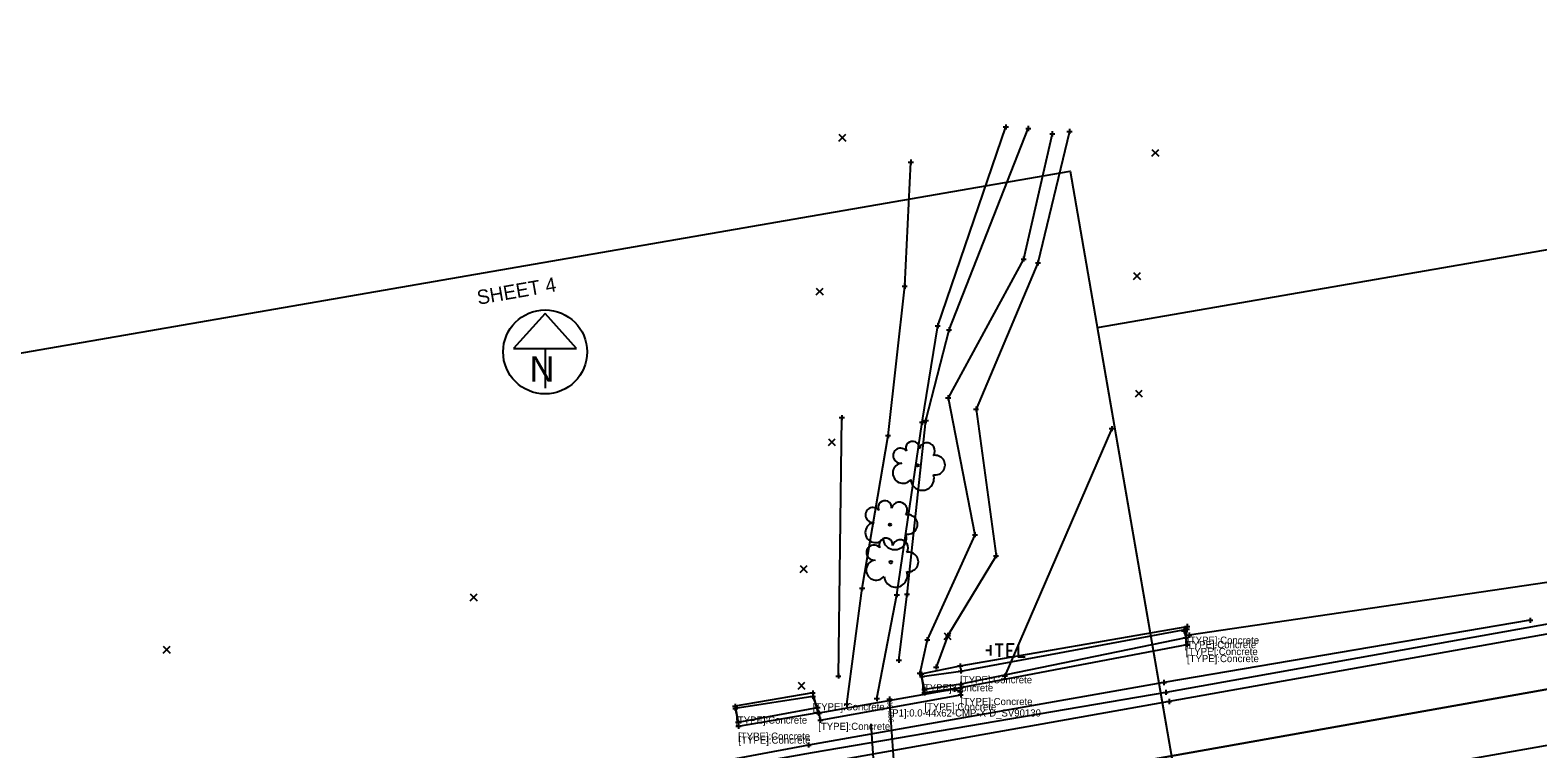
# Model space of a CAD drawing. Extents: x 1386013 to 1389776, y 604170 to 607009.
# Drawn here: x 1387481.7 to 1387776, y 604864.4 to 605004.7 of the extents above; entities that cross this region are included whole.
import ezdxf

# ---------------------------------------------------------------- set-up
doc = ezdxf.new("R2010")
doc.units = 0
for name, color, linetype in [('_CIVIL_CONSTRUCTION', 7, 'Continuous'), ('DR_X_Ditch', 7, 'Continuous'), ('DR_X_Headwall', 7, 'Continuous'), ('DR_X_Storm_Sewer', 7, 'Continuous'), ('DR_X_Text', 7, 'Continuous'), ('DV_X_Text', 7, 'Continuous'), ('PM_X_CL_Double_Solid', 7, 'Continuous'), ('PV_X_COP', 7, 'Continuous'), ('PV_X_EOP', 7, 'Continuous'), ('PV_X_Shoulder', 7, 'Continuous'), ('RD_X_Concrete_Pad', 7, 'Continuous'), ('RD_X_GR_Rt', 7, 'Continuous'), ('SC_Scratch1', 7, 'Continuous'), ('SH_Cut_Line', 7, 'Continuous'), ('SH_Masking', 7, 'Continuous'), ('SH_Text', 7, 'Continuous'), ('SV_X_Break_Lines', 7, 'Continuous'), ('SV_X_Random_Point', 7, 'Continuous'), ('SV_X_Text', 7, 'Continuous'), ('SV_X_Toe_of_Slope', 7, 'Continuous'), ('SV_X_Top_of_Bank', 7, 'Continuous'), ('UT_X_Telecom_Cells', 7, 'Continuous'), ('VG_X_Tree_Line_Lt', 7, 'Continuous')]:
    doc.layers.add(name, color=color, linetype=linetype)

msp = doc.modelspace()

# ---------------------------------------------------------------- linework, layer by layer
at = {"layer": '_CIVIL_CONSTRUCTION'}
for centre in [(1387654.95, 604919.77), (1387649.56, 604908.18), (1387649.74, 604900.87)]:
    msp.add_circle(centre, 0.24, dxfattribs=at)
for centre, radius, start, end in [((1387653.96, 604923.14), 1.32, 354.0047, 205.9741), ((1387656.77, 604922.6), 1.55, 323.83, 165.0376), ((1387651.64, 604921.64), 1.47, 39.0625, 279.5412), ((1387658.41, 604919.81), 1.91, 259.1453, 101.4596), ((1387652.09, 604918.23), 1.97, 96.1722, 320.5737), ((1387655.89, 604917.17), 2.28, 184.9476, 19.4572), ((1387648.58, 604911.55), 1.32, 354.0047, 205.9741), ((1387651.39, 604911.01), 1.55, 323.83, 165.0376), ((1387646.25, 604910.05), 1.47, 39.0625, 279.5412), ((1387653.02, 604908.22), 1.91, 259.1453, 101.4596), ((1387646.71, 604906.64), 1.97, 96.1722, 320.5737), ((1387650.51, 604905.58), 2.28, 184.9476, 19.4572), ((1387646.43, 604902.73), 1.47, 39.0625, 279.5412), ((1387648.76, 604904.24), 1.32, 354.0047, 205.9741), ((1387651.57, 604903.7), 1.55, 323.83, 165.0376), ((1387653.2, 604900.9), 1.91, 259.1453, 101.4596), ((1387646.89, 604899.32), 1.97, 96.1722, 320.5737), ((1387650.69, 604898.26), 2.28, 184.9476, 19.4572)]:
    msp.add_arc(centre, radius, start, end, dxfattribs=at)
at = {"layer": 'DR_X_Ditch'}
msp.add_lwpolyline([(1387651.29, 604881.71), (1387652.9, 604894.64), (1387656.56, 604928.52), (1387661.1, 604946.25), (1387676.57, 604985.54)], dxfattribs=at)
at = {"layer": 'DR_X_Headwall'}
msp.add_lwpolyline([(1387663.37, 604874.95), (1387663.27, 604875.61), (1387662.16, 604876.05), (1387635.68, 604871.35), (1387635.97, 604870.02)], close=True, dxfattribs=at)
at = {"layer": 'DR_X_Storm_Sewer'}
msp.add_line((1387652.33, 604833.62), (1387649.48, 604874.12), dxfattribs=at)
at = {"layer": 'DR_X_Text'}
msp.add_line((1387645.83, 604869.29), (1387647.75, 604841.89), dxfattribs=at)
at = {"layer": 'DV_X_Text'}
for p, q in [((1387671.69, 604985.84), (1387672.69, 604985.84)), ((1387672.19, 604986.34), (1387672.19, 604985.34)), ((1387672.19, 604985.84), (1387672.19, 604985.84)), ((1387676.07, 604985.54), (1387677.07, 604985.54)), ((1387676.57, 604986.04), (1387676.57, 604985.04)), ((1387676.57, 604985.54), (1387676.57, 604985.54)), ((1387684.62, 604985.47), (1387684.62, 604984.47)), ((1387680.75, 604984.48), (1387681.75, 604984.48)), ((1387681.25, 604984.98), (1387681.25, 604983.98)), ((1387681.25, 604984.48), (1387681.25, 604984.48)), ((1387684.12, 604984.97), (1387685.12, 604984.97)), ((1387684.62, 604984.97), (1387684.62, 604984.97)), ((1387653.65, 604979.48), (1387653.65, 604978.48)), ((1387653.15, 604978.98), (1387654.15, 604978.98)), ((1387653.65, 604978.98), (1387653.65, 604978.98)), ((1387675.15, 604960.04), (1387676.15, 604960.04)), ((1387675.65, 604960.54), (1387675.65, 604959.54)), ((1387675.65, 604960.04), (1387675.65, 604960.04)), ((1387677.95, 604959.27), (1387678.95, 604959.27)), ((1387678.45, 604959.77), (1387678.45, 604958.77)), ((1387678.45, 604959.27), (1387678.45, 604959.27)), ((1387651.95, 604954.74), (1387652.95, 604954.74)), ((1387652.45, 604955.24), (1387652.45, 604954.24)), ((1387652.45, 604954.74), (1387652.45, 604954.74)), ((1387658.38, 604947.02), (1387659.38, 604947.02)), ((1387658.88, 604947.52), (1387658.88, 604946.52)), ((1387658.88, 604947.02), (1387658.88, 604947.02)), ((1387660.6, 604946.25), (1387661.6, 604946.25)), ((1387661.1, 604946.75), (1387661.1, 604945.75)), ((1387661.1, 604946.25), (1387661.1, 604946.25)), ((1387660.42, 604932.95), (1387661.42, 604932.95)), ((1387660.92, 604933.45), (1387660.92, 604932.45)), ((1387660.92, 604932.95), (1387660.92, 604932.95)), ((1387640.17, 604929.59), (1387640.17, 604928.59)), ((1387665.88, 604930.75), (1387666.88, 604930.75)), ((1387666.38, 604931.25), (1387666.38, 604930.25)), ((1387666.38, 604930.75), (1387666.38, 604930.75)), ((1387639.67, 604929.09), (1387640.67, 604929.09)), ((1387640.17, 604929.09), (1387640.17, 604929.09)), ((1387655.34, 604928.17), (1387656.34, 604928.17)), ((1387655.84, 604928.67), (1387655.84, 604927.67)), ((1387655.84, 604928.17), (1387655.84, 604928.17)), ((1387656.06, 604928.52), (1387657.06, 604928.52)), ((1387656.56, 604929.02), (1387656.56, 604928.02)), ((1387656.56, 604928.52), (1387656.56, 604928.52)), ((1387692.37, 604926.94), (1387693.37, 604926.94)), ((1387692.87, 604927.44), (1387692.87, 604926.44)), ((1387692.87, 604926.94), (1387692.87, 604926.94)), ((1387648.7, 604925.6), (1387649.7, 604925.6)), ((1387649.2, 604926.1), (1387649.2, 604925.1)), ((1387649.2, 604925.6), (1387649.2, 604925.6)), ((1387665.66, 604906.21), (1387666.66, 604906.21)), ((1387666.16, 604906.71), (1387666.16, 604905.71)), ((1387666.16, 604906.21), (1387666.16, 604906.21)), ((1387669.77, 604902.11), (1387670.77, 604902.11)), ((1387670.27, 604902.61), (1387670.27, 604901.61)), ((1387670.27, 604902.11), (1387670.27, 604902.11)), ((1387643.65, 604895.81), (1387644.65, 604895.81)), ((1387644.15, 604896.31), (1387644.15, 604895.31)), ((1387644.15, 604895.81), (1387644.15, 604895.81)), ((1387650.4, 604894.51), (1387651.4, 604894.51)), ((1387650.9, 604895.01), (1387650.9, 604894.01)), ((1387650.9, 604894.51), (1387650.9, 604894.51)), ((1387652.4, 604894.64), (1387653.4, 604894.64)), ((1387652.9, 604895.14), (1387652.9, 604894.14)), ((1387652.9, 604894.64), (1387652.9, 604894.64)), ((1387707.08, 604888.33), (1387708.08, 604888.33)), ((1387707.52, 604888.28), (1387707.52, 604887.28)), ((1387707.58, 604888.83), (1387707.58, 604887.83)), ((1387707.58, 604888.33), (1387707.58, 604888.33)), ((1387774.07, 604889.52), (1387775.07, 604889.52)), ((1387774.57, 604890.02), (1387774.57, 604889.02)), ((1387774.57, 604889.52), (1387774.57, 604889.52)), ((1387656.35, 604885.71), (1387657.35, 604885.71)), ((1387656.85, 604886.21), (1387656.85, 604885.21)), ((1387656.85, 604885.71), (1387656.85, 604885.71)), ((1387660.39, 604886.56), (1387661.39, 604886.56)), ((1387660.89, 604887.06), (1387660.89, 604886.06)), ((1387660.89, 604886.56), (1387660.89, 604886.56)), ((1387706.51, 604887.46), (1387707.51, 604887.46)), ((1387706.81, 604886.11), (1387707.81, 604886.11)), ((1387706.81, 604886.11), (1387707.81, 604886.11)), ((1387707.01, 604887.96), (1387707.01, 604886.96)), ((1387707.01, 604887.46), (1387707.01, 604887.46)), ((1387707.02, 604887.78), (1387708.02, 604887.78)), ((1387707.31, 604886.61), (1387707.31, 604885.61)), ((1387707.31, 604886.61), (1387707.31, 604885.61)), ((1387707.31, 604886.11), (1387707.31, 604886.11)), ((1387707.31, 604886.11), (1387707.31, 604886.11)), ((1387707.5, 604886.6), (1387708.5, 604886.6)), ((1387707.52, 604887.78), (1387707.52, 604887.78)), ((1387707.54, 604885.24), (1387707.54, 604884.24)), ((1387708, 604887.1), (1387708, 604886.1)), ((1387708, 604886.6), (1387708, 604886.6)), ((1387651.29, 604882.21), (1387651.29, 604881.21)), ((1387707.04, 604884.74), (1387708.04, 604884.74)), ((1387707.54, 604884.74), (1387707.54, 604884.74)), ((1387650.79, 604881.71), (1387651.79, 604881.71)), ((1387651.29, 604881.71), (1387651.29, 604881.71)), ((1387655.39, 604879.66), (1387655.39, 604878.66)), ((1387655.67, 604879.53), (1387655.67, 604878.53)), ((1387658.08, 604880.38), (1387659.08, 604880.38)), ((1387658.58, 604880.88), (1387658.58, 604879.88)), ((1387658.58, 604880.38), (1387658.58, 604880.38)), ((1387662.76, 604880.6), (1387663.76, 604880.6)), ((1387662.88, 604879.61), (1387663.88, 604879.61)), ((1387663.26, 604881.1), (1387663.26, 604880.1)), ((1387663.26, 604880.6), (1387663.26, 604880.6)), ((1387663.38, 604880.11), (1387663.38, 604879.11)), ((1387663.38, 604879.61), (1387663.38, 604879.61)), ((1387639, 604878.63), (1387640, 604878.63)), ((1387639.5, 604879.13), (1387639.5, 604878.13)), ((1387639.5, 604878.63), (1387639.5, 604878.63)), ((1387654.89, 604879.16), (1387655.89, 604879.16)), ((1387655.17, 604879.03), (1387656.17, 604879.03)), ((1387655.31, 604878.52), (1387656.31, 604878.52)), ((1387655.39, 604879.16), (1387655.39, 604879.16)), ((1387655.67, 604879.03), (1387655.67, 604879.03)), ((1387655.81, 604879.02), (1387655.81, 604878.02)), ((1387655.81, 604878.52), (1387655.81, 604878.52)), ((1387656.31, 604876.52), (1387656.31, 604875.52)), ((1387662.16, 604876.55), (1387662.16, 604875.55)), ((1387662.85, 604876.35), (1387663.85, 604876.35)), ((1387662.93, 604877.01), (1387663.93, 604877.01)), ((1387663.35, 604876.85), (1387663.35, 604875.85)), ((1387663.35, 604876.35), (1387663.35, 604876.35)), ((1387663.43, 604877.51), (1387663.43, 604876.51)), ((1387663.43, 604877.01), (1387663.43, 604877.01)), ((1387671.49, 604878.65), (1387672.49, 604878.65)), ((1387671.99, 604879.15), (1387671.99, 604878.15)), ((1387671.99, 604878.65), (1387671.99, 604878.65)), ((1387702.54, 604877.37), (1387703.54, 604877.37)), ((1387703.04, 604877.87), (1387703.04, 604876.87)), ((1387703.04, 604877.37), (1387703.04, 604877.37)), ((1387633.98, 604875.32), (1387634.98, 604875.32)), ((1387634.01, 604874.66), (1387635.01, 604874.66)), ((1387634.48, 604875.82), (1387634.48, 604874.82)), ((1387634.48, 604875.32), (1387634.48, 604875.32)), ((1387634.51, 604875.16), (1387634.51, 604874.16)), ((1387634.51, 604874.66), (1387634.51, 604874.66)), ((1387641.12, 604873.64), (1387641.12, 604872.64)), ((1387646.5, 604874.25), (1387647.5, 604874.25)), ((1387647, 604874.75), (1387647, 604873.75)), ((1387647, 604874.25), (1387647, 604874.25)), ((1387648.98, 604874.12), (1387649.98, 604874.12)), ((1387649.48, 604874.62), (1387649.48, 604873.62)), ((1387649.48, 604874.12), (1387649.48, 604874.12)), ((1387655.78, 604875.33), (1387656.78, 604875.33)), ((1387655.81, 604876.02), (1387656.81, 604876.02)), ((1387656.28, 604875.83), (1387656.28, 604874.83)), ((1387656.28, 604875.33), (1387656.28, 604875.33)), ((1387656.31, 604876.02), (1387656.31, 604876.02)), ((1387661.66, 604876.05), (1387662.66, 604876.05)), ((1387662.16, 604876.05), (1387662.16, 604876.05)), ((1387662.77, 604875.61), (1387663.77, 604875.61)), ((1387662.87, 604874.95), (1387663.87, 604874.95)), ((1387663.27, 604876.11), (1387663.27, 604875.11)), ((1387663.27, 604875.61), (1387663.27, 604875.61)), ((1387663.37, 604875.45), (1387663.37, 604874.45)), ((1387663.37, 604874.95), (1387663.37, 604874.95)), ((1387702.89, 604875.43), (1387703.89, 604875.43)), ((1387703.39, 604875.93), (1387703.39, 604874.93)), ((1387703.39, 604875.43), (1387703.39, 604875.43)), ((1387703.54, 604873.65), (1387704.54, 604873.65)), ((1387704.04, 604874.15), (1387704.04, 604873.15)), ((1387704.04, 604873.65), (1387704.04, 604873.65)), ((1387618.85, 604872.73), (1387619.85, 604872.73)), ((1387618.86, 604872.32), (1387619.86, 604872.32)), ((1387619.35, 604873.23), (1387619.35, 604872.23)), ((1387619.35, 604872.73), (1387619.35, 604872.73)), ((1387619.36, 604872.82), (1387619.36, 604871.82)), ((1387619.36, 604872.32), (1387619.36, 604872.32)), ((1387634.92, 604872.49), (1387635.92, 604872.49)), ((1387635.06, 604871.51), (1387636.06, 604871.51)), ((1387635.18, 604871.35), (1387636.18, 604871.35)), ((1387635.42, 604872.99), (1387635.42, 604871.99)), ((1387635.42, 604872.49), (1387635.42, 604872.49)), ((1387635.56, 604872.01), (1387635.56, 604871.01)), ((1387635.56, 604871.51), (1387635.56, 604871.51)), ((1387635.68, 604871.85), (1387635.68, 604870.85)), ((1387635.68, 604871.35), (1387635.68, 604871.35)), ((1387635.97, 604870.52), (1387635.97, 604869.52)), ((1387640.62, 604873.14), (1387641.62, 604873.14)), ((1387641.12, 604873.14), (1387641.12, 604873.14)), ((1387619.42, 604869.59), (1387620.42, 604869.59)), ((1387619.42, 604869.59), (1387620.42, 604869.59)), ((1387619.5, 604868.82), (1387620.5, 604868.82)), ((1387619.92, 604870.09), (1387619.92, 604869.09)), ((1387619.92, 604870.09), (1387619.92, 604869.09)), ((1387619.92, 604869.59), (1387619.92, 604869.59)), ((1387619.92, 604869.59), (1387619.92, 604869.59)), ((1387620, 604869.32), (1387620, 604868.32)), ((1387620, 604868.82), (1387620, 604868.82)), ((1387635.47, 604870.02), (1387636.47, 604870.02)), ((1387635.97, 604870.02), (1387635.97, 604870.02)), ((1387633.15, 604865.16), (1387634.15, 604865.16)), ((1387633.65, 604865.66), (1387633.65, 604864.66)), ((1387633.65, 604865.16), (1387633.65, 604865.16))]:
    msp.add_line(p, q, dxfattribs=at)
at = {"layer": 'PM_X_CL_Double_Solid'}
msp.add_lwpolyline([(1386941.92, 604730.57), (1387000.37, 604739.9), (1387059.38, 604750.41), (1387127.32, 604761.93), (1387175.52, 604769.9), (1387233.31, 604779.13), (1387291.85, 604789.88), (1387343.04, 604798.39), (1387403.9, 604809.05), (1387458.49, 604818.93), (1387516.12, 604829.58), (1387574.82, 604839.73), (1387636.99, 604851.11), (1387704.35, 604863.01), (1387787.5, 604877.74), (1387859.73, 604890.76), (1387934.47, 604903.86), (1387998.85, 604914.97), (1388072.27, 604927.44)], dxfattribs=at)
at = {"layer": 'PV_X_COP'}
msp.add_lwpolyline([(1388072.27, 604927.44), (1387998.85, 604914.97), (1387934.47, 604903.86), (1387859.73, 604890.76), (1387787.5, 604877.74), (1387704.35, 604863.01), (1387636.99, 604851.11), (1387574.82, 604839.73), (1387516.12, 604829.58), (1387458.49, 604818.93), (1387403.9, 604809.05), (1387343.04, 604798.39), (1387291.85, 604789.88), (1387233.31, 604779.13), (1387175.52, 604769.9), (1387127.32, 604761.93), (1387059.38, 604750.41), (1387000.37, 604739.9), (1386941.92, 604730.57)], dxfattribs=at)
at = {"layer": 'PV_X_EOP'}
for points in [[(1388070.9, 604937.92), (1387997.67, 604925.46), (1387932.45, 604914.15), (1387857.85, 604900.92), (1387785.1, 604888.09), (1387704.04, 604873.65), (1387634.94, 604861.37), (1387573.23, 604850.33), (1387514.48, 604840.1), (1387457.17, 604829.65), (1387402.44, 604819.9), (1387341.38, 604808.9), (1387290.36, 604800.04), (1387231.98, 604789.91), (1387174.35, 604780.15), (1387125.76, 604771.91), (1387057.82, 604760.3), (1386999.09, 604750.97), (1386941.41, 604741.04)], [(1388073.48, 604916.74), (1388000.2, 604904.18), (1387936.61, 604893.17), (1387861, 604879.89), (1387788.15, 604866.91), (1387706.18, 604852.38), (1387637.62, 604840.16), (1387577.04, 604829.26), (1387518.08, 604818.58), (1387459.96, 604808.24), (1387405.36, 604798.5), (1387345.11, 604787.75), (1387291.8, 604778.43), (1387234.86, 604768.47), (1387177.43, 604758.7), (1387129.4, 604750.56), (1387061.72, 604739.2), (1387002.9, 604729.17), (1386943.42, 604719.4)]]:
    msp.add_lwpolyline(points, dxfattribs=at)
at = {"layer": 'PV_X_Shoulder'}
msp.add_lwpolyline([(1388070.88, 604939.75), (1387997.08, 604927.24), (1387932.1, 604916.23), (1387857.34, 604902.99), (1387785.16, 604890.04), (1387703.39, 604875.43), (1387634.35, 604863.66), (1387572.42, 604852.64), (1387514.1, 604842.11), (1387456.78, 604832.26), (1387401.91, 604822.43), (1387340.63, 604811.34), (1387290.11, 604802.67), (1387231.45, 604791.93), (1387174.18, 604782.71), (1387125.33, 604774.1), (1387057.54, 604762.26), (1386998.59, 604752.7), (1386940.97, 604743.32)], dxfattribs=at)
at = {"layer": 'RD_X_Concrete_Pad'}
for points in [[(1387707.58, 604888.33), (1387707.01, 604887.46), (1387707.31, 604886.11), (1387707.54, 604884.74), (1387663.35, 604876.35), (1387656.28, 604875.33), (1387655.67, 604879.03), (1387663.26, 604880.6)], [(1387619.35, 604872.73), (1387619.92, 604869.59), (1387620, 604868.82), (1387635.56, 604871.51), (1387634.48, 604875.32)]]:
    msp.add_lwpolyline(points, close=True, dxfattribs=at)
at = {"layer": 'RD_X_GR_Rt'}
msp.add_lwpolyline([(1387774.57, 604889.52), (1387703.04, 604877.37), (1387633.65, 604865.16), (1387573.86, 604853.92)], dxfattribs=at)
at = {"layer": 'SH_Cut_Line'}
for points in [[(1387727.6, 604729.92), (1387690.05, 604946.7), (1388025.06, 605004.73), (1388062.61, 604787.96)], [(1387387.31, 604702.37), (1387349.76, 604919.15), (1387684.77, 604977.18), (1387722.32, 604760.41)]]:
    msp.add_lwpolyline(points, close=True, dxfattribs=at)
at = {"layer": 'SH_Masking'}
msp.add_circle((1387582.25, 604941.9), 8.2, dxfattribs=at)
at = {"layer": 'SH_Text'}
for p, q in [((1387582.25, 604949.38), (1387576.1, 604942.55)), ((1387588.4, 604942.55), (1387582.25, 604949.38)), ((1387576.1, 604942.55), (1387588.4, 604942.55)), ((1387582.25, 604942.55), (1387582.25, 604934.82))]:
    msp.add_line(p, q, dxfattribs=at)
msp.add_circle((1387582.25, 604941.9), 8.2, dxfattribs=at)
at = {"layer": 'SV_X_Break_Lines'}
for points in [[(1387707.52, 604887.78), (1387707.31, 604886.11), (1387663.43, 604877.01), (1387656.31, 604876.02), (1387655.81, 604878.52), (1387663.38, 604879.61)], [(1387619.36, 604872.32), (1387619.92, 604869.59), (1387635.42, 604872.49), (1387634.51, 604874.66)]]:
    msp.add_lwpolyline(points, close=True, dxfattribs=at)
at = {"layer": 'SV_X_Random_Point'}
for p, q in [((1387639.59, 604983.08), (1387640.92, 604984.41)), ((1387639.59, 604984.41), (1387640.92, 604983.08)), ((1387700.71, 604980.13), (1387702.04, 604981.46)), ((1387700.71, 604981.46), (1387702.04, 604980.13)), ((1387697.14, 604956.07), (1387698.48, 604957.4)), ((1387697.14, 604957.4), (1387698.48, 604956.07)), ((1387635.18, 604953.04), (1387636.51, 604954.37)), ((1387635.18, 604954.37), (1387636.51, 604953.04)), ((1387697.48, 604933.12), (1387698.82, 604934.45)), ((1387697.48, 604934.45), (1387698.82, 604933.12)), ((1387637.57, 604923.62), (1387638.9, 604924.96)), ((1387637.57, 604924.96), (1387638.9, 604923.62)), ((1387632.04, 604898.85), (1387633.38, 604900.18)), ((1387632.04, 604900.18), (1387633.38, 604898.85)), ((1387567.63, 604893.32), (1387568.96, 604894.65)), ((1387567.63, 604894.65), (1387568.96, 604893.32)), ((1387660.14, 604885.73), (1387661.48, 604887.06)), ((1387660.14, 604887.06), (1387661.48, 604885.73)), ((1387507.7, 604883.1), (1387509.04, 604884.44)), ((1387507.7, 604884.44), (1387509.04, 604883.1)), ((1387631.62, 604876.09), (1387632.96, 604877.43)), ((1387631.62, 604877.43), (1387632.96, 604876.09))]:
    msp.add_line(p, q, dxfattribs=at)
at = {"layer": 'SV_X_Toe_of_Slope'}
for points in [[(1387647, 604874.25), (1387650.9, 604894.51), (1387655.84, 604928.17), (1387658.88, 604947.02), (1387672.19, 604985.84)], [(1387681.25, 604984.48), (1387675.65, 604960.04), (1387660.92, 604932.95), (1387666.16, 604906.21), (1387656.85, 604885.71), (1387655.39, 604879.16)], [(1388017.86, 604937.27), (1387957.48, 604928.09), (1387930.19, 604924.57), (1387856.89, 604908.62), (1387783.98, 604897.78), (1387708, 604886.6)]]:
    msp.add_lwpolyline(points, dxfattribs=at)
at = {"layer": 'SV_X_Top_of_Bank'}
for points in [[(1387684.62, 604984.97), (1387678.45, 604959.27), (1387666.38, 604930.75), (1387670.27, 604902.11), (1387660.89, 604886.56), (1387658.58, 604880.38)], [(1387641.12, 604873.14), (1387644.15, 604895.81), (1387649.2, 604925.6), (1387652.45, 604954.74), (1387653.65, 604978.98)]]:
    msp.add_lwpolyline(points, dxfattribs=at)
at = {"layer": 'UT_X_Telecom_Cells'}
for p, q in [((1387669.28, 604883.63), (1387668.28, 604883.63)), ((1387669.28, 604882.63), (1387669.28, 604884.63))]:
    msp.add_line(p, q, dxfattribs=at)
for points in [[(1387670.09, 604884.88), (1387671.65, 604884.88)], [(1387670.88, 604884.88), (1387670.88, 604882.38)], [(1387673.79, 604884.88), (1387672.44, 604884.88), (1387672.44, 604882.38), (1387673.89, 604882.38)], [(1387672.44, 604883.64), (1387673.4, 604883.64)], [(1387674.58, 604884.88), (1387674.58, 604882.38), (1387675.94, 604882.38)]]:
    msp.add_lwpolyline(points, dxfattribs=at)
at = {"layer": 'VG_X_Tree_Line_Lt'}
for points in [[(1387639.5, 604878.63), (1387640.17, 604929.09)], [(1387692.87, 604926.94), (1387671.99, 604878.65)]]:
    msp.add_lwpolyline(points, dxfattribs=at)

# ---------------------------------------------------------------- texts
at = {"layer": 'SC_Scratch1'}
msp.add_text("907.86'", height=1, rotation=94.0202, dxfattribs=at).set_placement((1387650.3, 604869.57))
at = {"layer": 'SH_Text'}
msp.add_text('SHEET 4', height=2.8, rotation=9.8279, dxfattribs=at).set_placement((1387569.2, 604951.11))
msp.add_text('N', height=5, dxfattribs=at).set_placement((1387579.22, 604936.07))
at = {"layer": 'SV_X_Text'}
for s, p in [('[TYPE]:Concrete', (1387707.01, 604884.06)), ('[TYPE]:Concrete', (1387707.58, 604884.93)), ('[TYPE]:Concrete', (1387707.31, 604882.71)), ('[TYPE]:Concrete', (1387707.54, 604881.34)), ('[TYPE]:Concrete', (1387655.67, 604875.63)), ('[TYPE]:Concrete', (1387663.26, 604877.2)), ('[TYPE]:Concrete', (1387634.48, 604871.92)), ('[TYPE]:Concrete', (1387656.28, 604871.93)), ('[TYPE]:Concrete', (1387663.35, 604872.95)), ('[TYPE]:Concrete', (1387619.35, 604869.33)), ('[P1]:0.0-44x62-CMP-X-D_SV90130', (1387649.48, 604870.72)), ('[TYPE]:Concrete', (1387619.92, 604866.19)), ('[TYPE]:Concrete', (1387635.56, 604868.11)), ('[TYPE]:Concrete', (1387620, 604865.42))]:
    msp.add_text(s, height=1.4, dxfattribs=at).set_placement(p)

doc.saveas('drawing.dxf')
